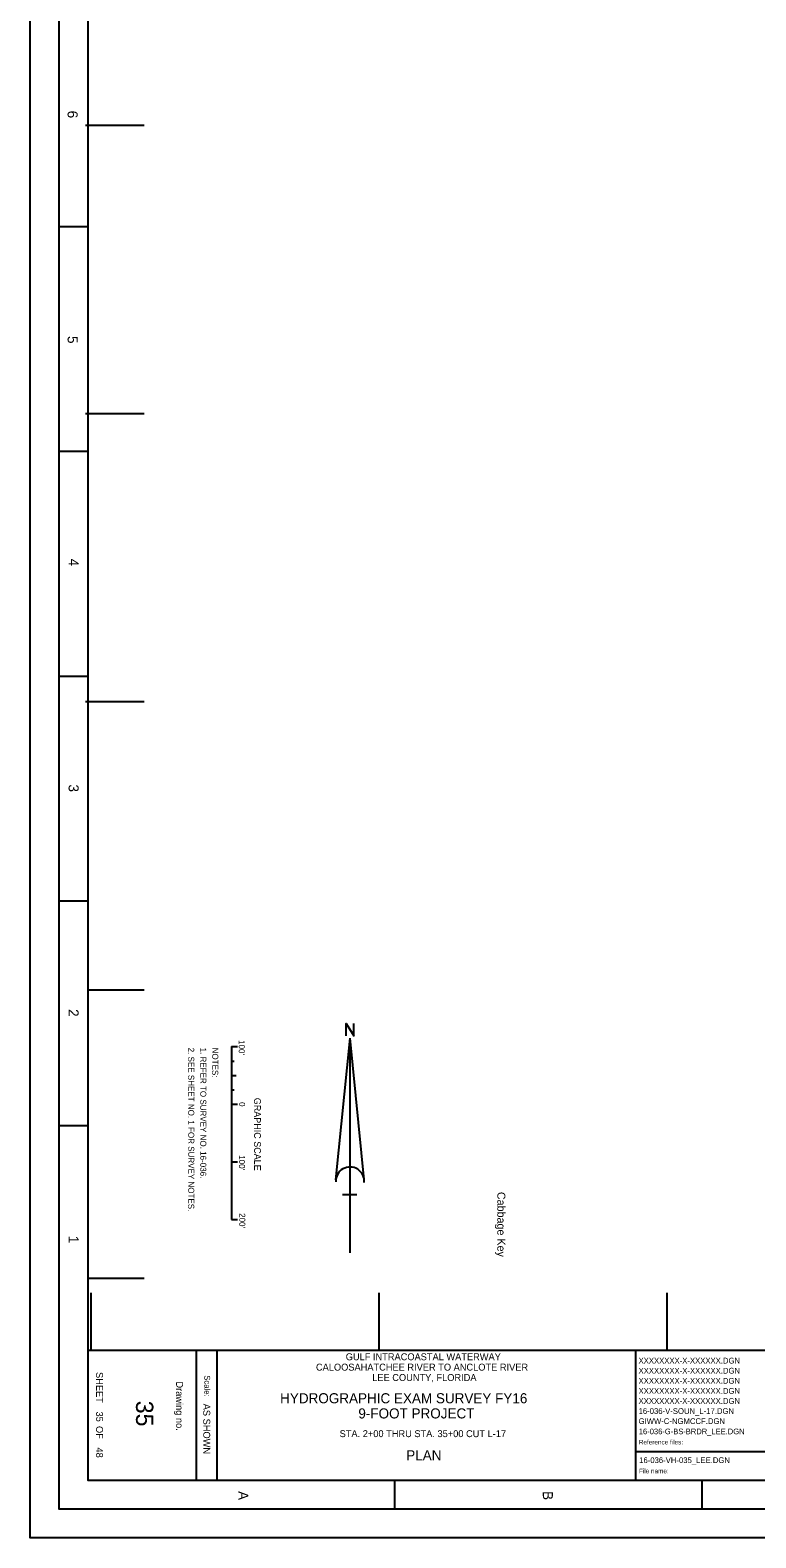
# Model space of a CAD drawing. Extents: x 582894 to 586294, y 843549 to 847949.
# Drawn here: x 582894 to 584154, y 843549 to 846165 of the extents above; entities that cross this region are included whole.
import ezdxf

# ---------------------------------------------------------------- set-up
doc = ezdxf.new("R2010")
doc.units = 0
for name, color, linetype in [('G-ANNO-NPLT', 7, 'Continuous'), ('G-ANNO-TEXT-DRWG', 7, 'Continuous'), ('G-ANNO-TEXT-PROJ', 7, 'Continuous'), ('G-ANNO-TEXT-TTLB', 7, 'Continuous'), ('G-ANNO-TTLB', 7, 'Continuous'), ('V-ANNO-NOTE', 7, 'Continuous'), ('V-ANNO-SYMB', 7, 'Continuous'), ('V-SITE-IDEN', 7, 'Continuous'), ('V-TOPO-COOR-STAT', 7, 'Continuous')]:
    doc.layers.add(name, color=color, linetype=linetype)

msp = doc.modelspace()

# ---------------------------------------------------------------- linework, layer by layer
at = {"layer": 'G-ANNO-NPLT'}
msp.add_lwpolyline([(586294, 847949.5), (586294, 843549.5), (582894, 843549.5), (582894, 847949.5)], close=True, dxfattribs=at)
msp.add_lwpolyline([(582944, 843549.4), (582894, 843549.4), (582894, 843599.4)], dxfattribs=at)
at = {"layer": 'G-ANNO-TTLB'}
for p, q in [((582944, 845824.5), (582994, 845824.5)), ((582944, 845434.5), (582994, 845434.5)), ((582944, 845044.5), (582994, 845044.5)), ((582944, 844654.5), (582994, 844654.5)), ((582944, 844264.5), (582994, 844264.5)), ((586194, 843874.5), (582994, 843874.5)), ((583182.1, 843874.5), (583182.1, 843649.5)), ((583217.8, 843874.5), (583217.8, 843649.5)), ((583944.8, 843874.5), (583944.8, 843649.5)), ((584296.1, 843698.8), (583944.8, 843698.8)), ((583527.3, 843599.5), (583527.3, 843649.5)), ((584060.6, 843599.5), (584060.6, 843649.5))]:
    msp.add_line(p, q, dxfattribs=at)
for points in [[(582944, 847899.5), (582944, 843599.5), (586244, 843599.5), (586244, 847899.5)], [(586194, 843649.5), (586194, 847774.5), (582994, 847774.5), (582994, 843649.5)]]:
    msp.add_lwpolyline(points, close=True, dxfattribs=at)
at = {"layer": 'V-ANNO-NOTE'}
for p, q in [((583243.3, 844401.6), (583243.3, 844101.6)), ((583243.3, 844401.6), (583253.8, 844401.6)), ((583243.3, 844376.6), (583248.1, 844376.6)), ((583243.3, 844351.6), (583251.9, 844351.6)), ((583243.3, 844326.6), (583248.1, 844326.6)), ((583243.3, 844301.6), (583253.8, 844301.6)), ((583243.3, 844301.6), (583248.3, 844301.6)), ((583243.3, 844301.6), (583253.8, 844301.6)), ((583243.3, 844201.6), (583253.8, 844201.6)), ((583243.3, 844101.6), (583253.8, 844101.6))]:
    msp.add_line(p, q, dxfattribs=at)
at = {"layer": 'V-ANNO-SYMB'}
for p, q in [((583424.5, 844170.4), (583449.2, 844416.2)), ((583449.2, 844043.8), (583449.2, 844416.2)), ((583473.9, 844170.4), (583449.2, 844416.2)), ((583460.9, 844144.4), (583436.1, 844144.4))]:
    msp.add_line(p, q, dxfattribs=at)
msp.add_lwpolyline([(583442.3, 844420.1), (583442.3, 844441.9), (583455.8, 844420.1), (583455.8, 844441.9)], dxfattribs=at)
msp.add_arc((583449.2, 844167.9), 24.8, 355.2984, 182.0673, dxfattribs=at)
at = {"layer": 'V-TOPO-COOR-STAT'}
for p, q in [((582990.2, 846000), (583092.2, 846000)), ((582990.2, 845500), (583092.2, 845500)), ((582990.2, 845000), (583092.2, 845000)), ((582994, 844500), (583092.2, 844500)), ((582994, 844000), (583092.2, 844000)), ((583000, 843874.5), (583000, 843974.5)), ((583500, 843874.5), (583500, 843974.5)), ((584000, 843874.5), (584000, 843974.5))]:
    msp.add_line(p, q, dxfattribs=at)

# ---------------------------------------------------------------- texts
at = {"layer": 'G-ANNO-TEXT-DRWG'}
for s, height, rotation, p in [('XXXXXXXX-X-XXXXXX.DGN', 10, 360, (583950.1, 843851.8)), ('XXXXXXXX-X-XXXXXX.DGN', 10, 360, (583950.1, 843834.3)), ('XXXXXXXX-X-XXXXXX.DGN', 10, 360, (583950.1, 843816.8)), ('XXXXXXXX-X-XXXXXX.DGN', 10, 360, (583950.1, 843799.3)), ('35', 30, 270, (583077.8, 843787.2)), ('XXXXXXXX-X-XXXXXX.DGN', 10, 360, (583950.1, 843781.8)), ('16-036-V-SOUN_L-17.DGN', 10, 360, (583950.1, 843764.3)), (' 35          48', 12, 270, (583008.5, 843773)), ('GIWW-C-NGMCCF.DGN', 10, 360, (583950.1, 843746.8)), ('STA. 2+00 THRU STA. 35+00 CUT L-17', 12, 360, (583431.2, 843724.1)), ('PLAN', 17.5, 360, (583546.8, 843683.9)), ('16-036-VH-035_LEE.DGN', 10, 360, (583951.1, 843679.1))]:
    msp.add_text(s, height=height, rotation=rotation, dxfattribs=at).set_placement(p)
at = {"layer": 'G-ANNO-TEXT-PROJ'}
for s, height, p in [('GULF INTRACOASTAL WATERWAY', 12, (583441.8, 843857.5)), ('CALOOSAHATCHEE RIVER TO ANCLOTE RIVER', 12, (583390.1, 843839.5)), ('LEE COUNTY, FLORIDA', 12, (583487.8, 843821.5)), ('HYDROGRAPHIC EXAM SURVEY FY16', 17.5, (583327.9, 843782.8)), ('9-FOOT PROJECT', 17.5, (583463.7, 843756.5)), ('16-036-G-BS-BRDR_LEE.DGN', 9.8, (583950.5, 843729.1))]:
    msp.add_text(s, height=height, rotation=360, dxfattribs=at).set_placement(p)
at = {"layer": 'G-ANNO-TEXT-TTLB'}
for s, height, rotation, p in [('SHEET         OF', 12, 270, (583008.5, 843837)), ('Scale:', 10, 270, (583196.4, 843831.4)), ('Drawing no.', 12, 270, (583147.4, 843820.7)), ('AS SHOWN', 12, 270, (583194.5, 843782.1)), ('Reference files:', 8, 360, (583950.6, 843711.4)), ('File name:', 8, 360, (583950.8, 843661.4))]:
    msp.add_text(s, height=height, rotation=rotation, dxfattribs=at).set_placement(p)
at = {"layer": 'G-ANNO-TTLB'}
for s, p in [('6', (582959, 846025.2)), ('5', (582959, 845634.3)), ('4', (582960.7, 845248.2)), ('3', (582960.7, 844856.3)), ('2', (582960.7, 844466.6)), ('1', (582960.7, 844073.4)), ('A', (583255.2, 843630.5)), ('B', (583783.9, 843630.5))]:
    msp.add_text(s, height=17.5, rotation=270, dxfattribs=at).set_placement(p)
at = {"layer": 'V-ANNO-NOTE'}
for s, height, p in [("100'", 10.42, (583256.1, 844412.9)), ('2. SEE SHEET NO. 1 FOR SURVEY NOTES.', 10.416, (583168.4, 844399.8)), ('1. REFER TO SURVEY NO. 16-036.', 10.416, (583189.3, 844399.8)), ('NOTES:', 10.42, (583210.1, 844399.8)), ('0', 10.4, (583256.7, 844305.3)), ('GRAPHIC SCALE', 11.666, (583282.8, 844312.8)), ("100'", 10.42, (583256.5, 844213.2)), ("200'", 10.42, (583257, 844112.7))]:
    msp.add_text(s, height=height, rotation=270, dxfattribs=at).set_placement(p)
at = {"layer": 'V-SITE-IDEN'}
msp.add_text('Cabbage Key', height=13.92, rotation=270, dxfattribs=at).set_placement((583704.9, 844149.5))

doc.saveas('drawing.dxf')
